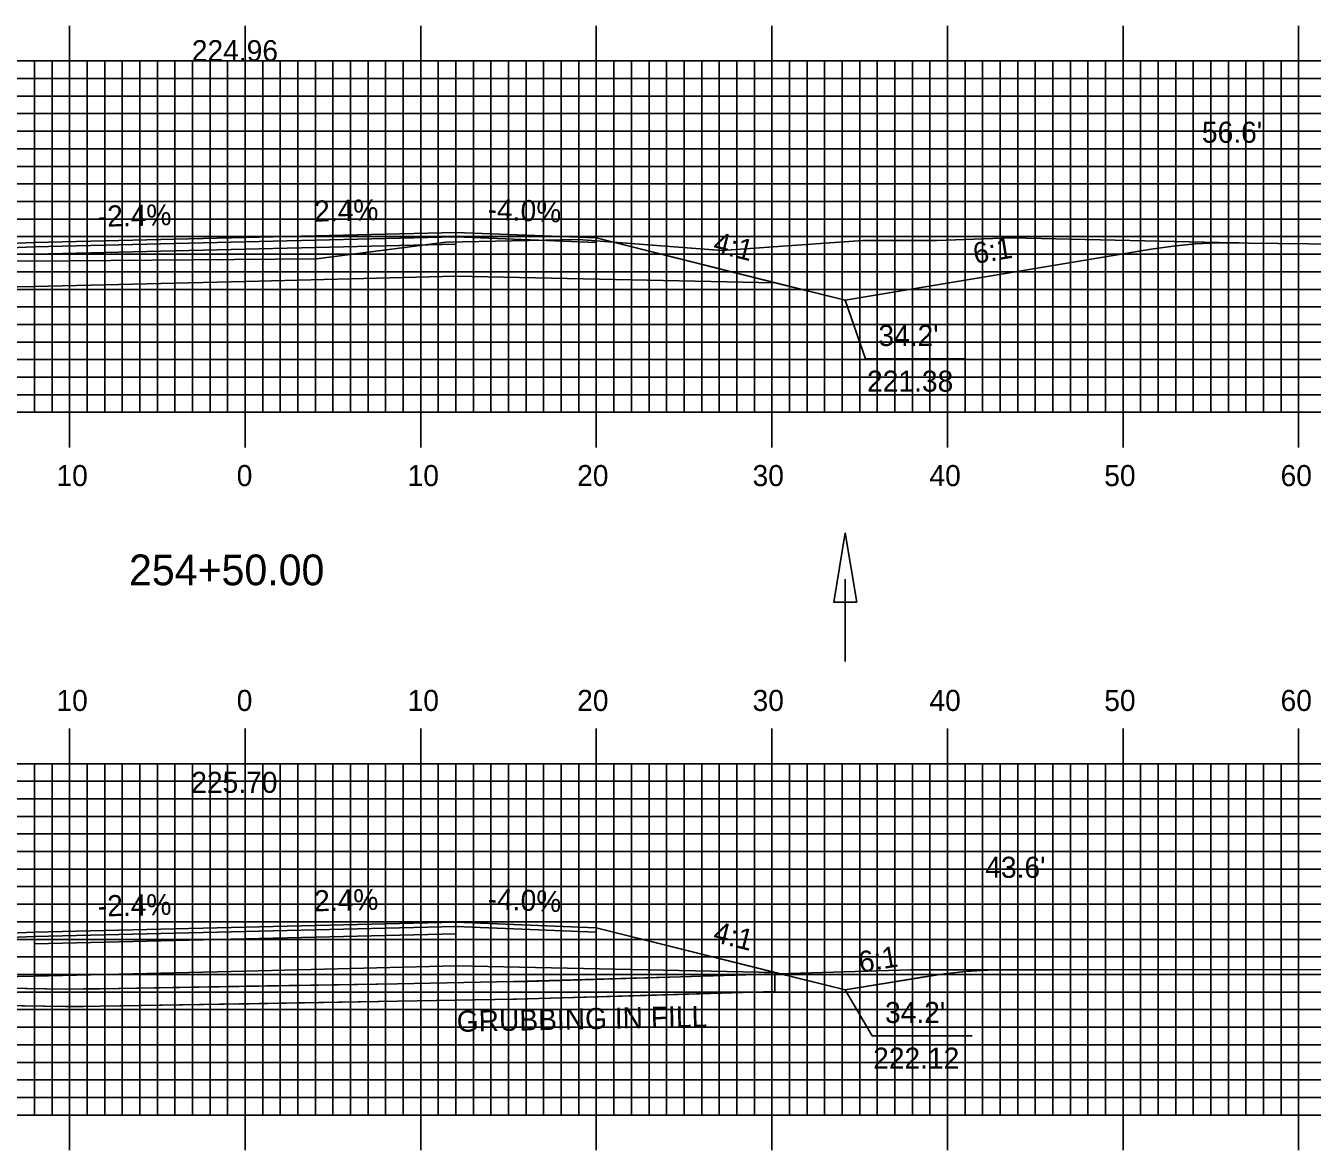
# Model space of a CAD drawing. Extents: x 1804684 to 1805027, y 442591 to 442811.
# Drawn here: x 1804837.2 to 1804910.5, y 442646.7 to 442710.7 of the extents above; entities that cross this region are included whole.
import ezdxf

# ---------------------------------------------------------------- set-up
doc = ezdxf.new("R2010")
doc.units = 0
for name, color, linetype in [('ANNOTATION', 7, 'Continuous'), ('D_Drainage_Ditch_Line', 7, 'Continuous'), ('D_Roadway_Centerline', 7, 'Continuous'), ('D_Roadway_Centerline_Text', 7, 'Continuous'), ('D_Roadway_Edge_Shoulder', 7, 'Continuous'), ('D_Roadway_Edge_TW', 7, 'Continuous'), ('D_Roadway_Pavement', 7, 'Continuous'), ('D_Roadway_SlopeLines', 7, 'Continuous'), ('D_Roadway_SubGrade', 7, 'Continuous'), ('D_Text_Standard', 7, 'Continuous'), ('GRUBBING IN FILL', 7, 'Continuous'), ('H_V ANNOTATION', 7, 'Continuous'), ('MAJOR', 7, 'Continuous'), ('MINOR', 7, 'Continuous'), ('S_Roadway_Centerline', 7, 'Continuous')]:
    doc.layers.add(name, color=color, linetype=linetype)

msp = doc.modelspace()

# ---------------------------------------------------------------- linework, layer by layer
at = {"layer": 'ANNOTATION'}
for points in [[(1804890.701, 442691.713), (1804885.009, 442691.713), (1804883.854, 442695.045)], [(1804891.08, 442653.178), (1804885.388, 442653.178), (1804883.854, 442655.787)]]:
    msp.add_lwpolyline(points, dxfattribs=at)
at = {"layer": 'D_Drainage_Ditch_Line'}
msp.add_line((1804883.855, 442679.177), (1804883.854, 442674.478), dxfattribs=at)
msp.add_lwpolyline([(1804884.511, 442677.865), (1804883.198, 442677.865), (1804883.855, 442681.802)], close=True, dxfattribs=at)
at = {"layer": 'D_Roadway_Centerline'}
for points in [[(1804797.853, 442696.978), (1804799.103, 442696.959), (1804800.353, 442696.886), (1804801.603, 442696.759), (1804802.853, 442696.578), (1804815.506, 442694.469), (1804819.506, 442695.469), (1804829.68, 442698.012), (1804837.68, 442698.332), (1804849.68, 442698.62), (1804861.68, 442698.908), (1804869.68, 442698.588), (1804879.854, 442696.045), (1804883.854, 442695.045), (1804901.287, 442697.95), (1804902.537, 442698.129), (1804903.787, 442698.249), (1804905.037, 442698.31), (1804906.287, 442698.313)], [(1804808.372, 442655.902), (1804809.622, 442655.911), (1804810.872, 442655.859), (1804812.122, 442655.744), (1804813.372, 442655.567), (1804815.506, 442655.211), (1804819.506, 442656.211), (1804829.68, 442658.755), (1804837.68, 442659.075), (1804849.68, 442659.363), (1804861.68, 442659.651), (1804869.68, 442659.331), (1804879.854, 442656.787), (1804883.854, 442655.787), (1804888.235, 442656.517), (1804889.485, 442656.7), (1804890.735, 442656.83), (1804891.985, 442656.909), (1804893.235, 442656.936)]]:
    msp.add_lwpolyline(points, dxfattribs=at)
at = {"layer": 'D_Roadway_Edge_Shoulder'}
for points in [[(1804861.68, 442698.908), (1804869.68, 442698.588), (1804869.68, 442698.338), (1804861.68, 442698.658)], [(1804837.68, 442698.332), (1804829.68, 442698.012), (1804829.68, 442697.762), (1804837.68, 442698.082)], [(1804837.68, 442659.075), (1804829.68, 442658.755), (1804829.68, 442658.505), (1804837.68, 442658.825)], [(1804861.68, 442659.651), (1804869.68, 442659.331), (1804869.68, 442659.081), (1804861.68, 442659.401)]]:
    msp.add_lwpolyline(points, close=True, dxfattribs=at)
at = {"layer": 'D_Roadway_Edge_TW'}
for points in [[(1804837.68, 442698.082), (1804837.68, 442698.332), (1804849.68, 442698.62), (1804861.68, 442698.908), (1804861.68, 442698.658), (1804849.68, 442698.37)], [(1804837.68, 442658.825), (1804837.68, 442659.075), (1804849.68, 442659.363), (1804861.68, 442659.651), (1804861.68, 442659.401), (1804849.68, 442659.113)]]:
    msp.add_lwpolyline(points, close=True, dxfattribs=at)
at = {"layer": 'D_Roadway_Pavement'}
for points in [[(1804837.68, 442697.666), (1804837.68, 442698.082), (1804849.68, 442698.37), (1804861.68, 442698.658), (1804861.68, 442698.242), (1804849.68, 442697.954)], [(1804837.68, 442658.408), (1804837.68, 442658.825), (1804849.68, 442659.113), (1804861.68, 442659.401), (1804861.68, 442658.984), (1804849.68, 442658.696)]]:
    msp.add_lwpolyline(points, close=True, dxfattribs=at)
at = {"layer": 'D_Roadway_SlopeLines'}
for points in [[(1804869.68, 442698.588), (1804883.854, 442695.045)], [(1804883.854, 442695.045), (1804901.287, 442697.95), (1804902.537, 442698.129), (1804903.787, 442698.249), (1804905.037, 442698.31), (1804906.287, 442698.313)], [(1804869.68, 442659.331), (1804883.854, 442655.787)], [(1804883.854, 442655.787), (1804888.235, 442656.517), (1804889.485, 442656.7), (1804890.735, 442656.83), (1804891.985, 442656.909), (1804893.235, 442656.936)], [(1804883.854, 442655.787), (1804889.485, 442656.7), (1804890.735, 442656.83), (1804891.985, 442656.909), (1804893.235, 442656.936)]]:
    msp.add_lwpolyline(points, dxfattribs=at)
at = {"layer": 'D_Roadway_SubGrade'}
for points in [[(1804837.68, 442695.832), (1804819.506, 442695.469), (1804829.68, 442698.012), (1804829.68, 442697.762), (1804837.68, 442698.082), (1804849.68, 442698.37), (1804861.68, 442698.658), (1804869.68, 442698.338), (1804869.68, 442698.588), (1804879.854, 442696.045), (1804861.68, 442696.408), (1804849.68, 442696.12)], [(1804837.68, 442656.574), (1804819.506, 442656.211), (1804829.68, 442658.755), (1804829.68, 442658.505), (1804837.68, 442658.825), (1804849.68, 442659.113), (1804861.68, 442659.401), (1804869.68, 442659.081), (1804869.68, 442659.331), (1804879.854, 442656.787), (1804861.68, 442657.15), (1804849.68, 442656.862)]]:
    msp.add_lwpolyline(points, close=True, dxfattribs=at)
at = {"layer": 'GRUBBING IN FILL'}
msp.add_line((1804879.854, 442656.699), (1804879.854, 442655.698), dxfattribs=at)
msp.add_line((1804879.854, 442656.699), (1804879.854, 442655.698), dxfattribs=at)
for points in [[(1804819.506, 442656.161), (1804828.421, 442656.017), (1804839.457, 442655.839), (1804841.418, 442655.854), (1804849.68, 442655.995), (1804849.68, 442654.995), (1804841.429, 442654.854), (1804839.454, 442654.839), (1804829.48, 442655), (1804819.506, 442655.161)], [(1804819.506, 442656.161), (1804828.421, 442656.017), (1804839.457, 442655.839), (1804841.418, 442655.854), (1804849.68, 442655.995), (1804849.68, 442654.995), (1804841.429, 442654.854), (1804839.454, 442654.839), (1804829.48, 442655), (1804819.506, 442655.161)], [(1804849.68, 442655.995), (1804858.363, 442656.143), (1804864.965, 442656.263), (1804874.47, 442656.536), (1804879.854, 442656.699), (1804879.854, 442655.698), (1804872.498, 442655.476), (1804865.047, 442655.258), (1804861.666, 442655.203), (1804858.38, 442655.143), (1804849.905, 442654.999), (1804849.68, 442654.995)], [(1804849.68, 442655.995), (1804858.363, 442656.143), (1804864.965, 442656.263), (1804874.47, 442656.536), (1804879.854, 442656.699), (1804879.854, 442655.698), (1804872.498, 442655.476), (1804865.047, 442655.258), (1804861.666, 442655.203), (1804858.38, 442655.143), (1804849.905, 442654.999), (1804849.68, 442654.995)]]:
    msp.add_lwpolyline(points, close=True, dxfattribs=at)
msp.add_lwpolyline([(1804819.506, 442655.161), (1804839.454, 442654.839), (1804840.476, 442654.849), (1804841.429, 442654.854), (1804858.38, 442655.143), (1804864.952, 442655.262), (1804865.142, 442655.254), (1804879.854, 442655.698)], dxfattribs=at)
msp.add_lwpolyline([(1804819.506, 442655.161), (1804839.454, 442654.839), (1804840.476, 442654.849), (1804841.429, 442654.854), (1804858.38, 442655.143), (1804864.952, 442655.262), (1804865.142, 442655.254), (1804879.854, 442655.698)], dxfattribs=at)
at = {"layer": 'MAJOR'}
for p, q in [((1804839.68, 442710.669), (1804839.68, 442708.665)), ((1804849.68, 442710.669), (1804849.68, 442708.665)), ((1804859.68, 442710.669), (1804859.68, 442708.665)), ((1804869.68, 442710.669), (1804869.68, 442708.665)), ((1804879.68, 442710.669), (1804879.68, 442708.665)), ((1804889.68, 442710.669), (1804889.68, 442708.665)), ((1804899.68, 442710.669), (1804899.68, 442708.665)), ((1804909.68, 442710.669), (1804909.68, 442708.665)), ((1804709.68, 442708.665), (1804989.68, 442708.665)), ((1804709.68, 442708.665), (1804989.68, 442708.665)), ((1804839.68, 442688.665), (1804839.68, 442708.665)), ((1804849.68, 442688.665), (1804849.68, 442708.665)), ((1804859.68, 442688.665), (1804859.68, 442708.665)), ((1804869.68, 442688.665), (1804869.68, 442708.665)), ((1804879.68, 442688.665), (1804879.68, 442708.665)), ((1804889.68, 442688.665), (1804889.68, 442708.665)), ((1804899.68, 442688.665), (1804899.68, 442708.665)), ((1804909.68, 442688.665), (1804909.68, 442708.665)), ((1804709.68, 442703.665), (1804989.68, 442703.665)), ((1804709.68, 442698.665), (1804989.68, 442698.665)), ((1804709.68, 442693.665), (1804989.68, 442693.665)), ((1804709.68, 442688.665), (1804989.68, 442688.665)), ((1804709.68, 442688.665), (1804989.68, 442688.665)), ((1804839.68, 442686.661), (1804839.68, 442688.665)), ((1804849.68, 442686.661), (1804849.68, 442688.665)), ((1804859.68, 442686.661), (1804859.68, 442688.665)), ((1804869.68, 442686.661), (1804869.68, 442688.665)), ((1804879.68, 442686.661), (1804879.68, 442688.665)), ((1804889.68, 442686.661), (1804889.68, 442688.665)), ((1804899.68, 442686.661), (1804899.68, 442688.665)), ((1804909.68, 442686.661), (1804909.68, 442688.665)), ((1804839.68, 442670.669), (1804839.68, 442668.665)), ((1804849.68, 442670.669), (1804849.68, 442668.665)), ((1804859.68, 442670.669), (1804859.68, 442668.665)), ((1804869.68, 442670.669), (1804869.68, 442668.665)), ((1804879.68, 442670.669), (1804879.68, 442668.665)), ((1804889.68, 442670.669), (1804889.68, 442668.665)), ((1804899.68, 442670.669), (1804899.68, 442668.665)), ((1804909.68, 442670.669), (1804909.68, 442668.665)), ((1804709.68, 442668.665), (1804989.68, 442668.665)), ((1804709.68, 442668.665), (1804989.68, 442668.665)), ((1804839.68, 442648.665), (1804839.68, 442668.665)), ((1804849.68, 442648.665), (1804849.68, 442668.665)), ((1804859.68, 442648.665), (1804859.68, 442668.665)), ((1804869.68, 442648.665), (1804869.68, 442668.665)), ((1804879.68, 442648.665), (1804879.68, 442668.665)), ((1804889.68, 442648.665), (1804889.68, 442668.665)), ((1804899.68, 442648.665), (1804899.68, 442668.665)), ((1804909.68, 442648.665), (1804909.68, 442668.665)), ((1804709.68, 442663.665), (1804989.68, 442663.665)), ((1804709.68, 442658.665), (1804989.68, 442658.665)), ((1804709.68, 442653.665), (1804989.68, 442653.665)), ((1804709.68, 442648.665), (1804989.68, 442648.665)), ((1804709.68, 442648.665), (1804989.68, 442648.665)), ((1804839.68, 442646.661), (1804839.68, 442648.665)), ((1804849.68, 442646.661), (1804849.68, 442648.665)), ((1804859.68, 442646.661), (1804859.68, 442648.665)), ((1804869.68, 442646.661), (1804869.68, 442648.665)), ((1804879.68, 442646.661), (1804879.68, 442648.665)), ((1804889.68, 442646.661), (1804889.68, 442648.665)), ((1804899.68, 442646.661), (1804899.68, 442648.665)), ((1804909.68, 442646.661), (1804909.68, 442648.665))]:
    msp.add_line(p, q, dxfattribs=at)
at = {"layer": 'MINOR'}
for p, q in [((1804837.68, 442688.665), (1804837.68, 442708.665)), ((1804838.68, 442688.665), (1804838.68, 442708.665)), ((1804840.68, 442688.665), (1804840.68, 442708.665)), ((1804841.68, 442688.665), (1804841.68, 442708.665)), ((1804842.68, 442688.665), (1804842.68, 442708.665)), ((1804843.68, 442688.665), (1804843.68, 442708.665)), ((1804844.68, 442688.665), (1804844.68, 442708.665)), ((1804845.68, 442688.665), (1804845.68, 442708.665)), ((1804846.68, 442688.665), (1804846.68, 442708.665)), ((1804847.68, 442688.665), (1804847.68, 442708.665)), ((1804848.68, 442688.665), (1804848.68, 442708.665)), ((1804850.68, 442688.665), (1804850.68, 442708.665)), ((1804851.68, 442688.665), (1804851.68, 442708.665)), ((1804852.68, 442688.665), (1804852.68, 442708.665)), ((1804853.68, 442688.665), (1804853.68, 442708.665)), ((1804854.68, 442688.665), (1804854.68, 442708.665)), ((1804855.68, 442688.665), (1804855.68, 442708.665)), ((1804856.68, 442688.665), (1804856.68, 442708.665)), ((1804857.68, 442688.665), (1804857.68, 442708.665)), ((1804858.68, 442688.665), (1804858.68, 442708.665)), ((1804860.68, 442688.665), (1804860.68, 442708.665)), ((1804861.68, 442688.665), (1804861.68, 442708.665)), ((1804862.68, 442688.665), (1804862.68, 442708.665)), ((1804863.68, 442688.665), (1804863.68, 442708.665)), ((1804864.68, 442688.665), (1804864.68, 442708.665)), ((1804865.68, 442688.665), (1804865.68, 442708.665)), ((1804866.68, 442688.665), (1804866.68, 442708.665)), ((1804867.68, 442688.665), (1804867.68, 442708.665)), ((1804868.68, 442688.665), (1804868.68, 442708.665)), ((1804870.68, 442688.665), (1804870.68, 442708.665)), ((1804871.68, 442688.665), (1804871.68, 442708.665)), ((1804872.68, 442688.665), (1804872.68, 442708.665)), ((1804873.68, 442688.665), (1804873.68, 442708.665)), ((1804874.68, 442688.665), (1804874.68, 442708.665)), ((1804875.68, 442688.665), (1804875.68, 442708.665)), ((1804876.68, 442688.665), (1804876.68, 442708.665)), ((1804877.68, 442688.665), (1804877.68, 442708.665)), ((1804878.68, 442688.665), (1804878.68, 442708.665)), ((1804880.68, 442688.665), (1804880.68, 442708.665)), ((1804881.68, 442688.665), (1804881.68, 442708.665)), ((1804882.68, 442688.665), (1804882.68, 442708.665)), ((1804883.68, 442688.665), (1804883.68, 442708.665)), ((1804884.68, 442688.665), (1804884.68, 442708.665)), ((1804885.68, 442688.665), (1804885.68, 442708.665)), ((1804886.68, 442688.665), (1804886.68, 442708.665)), ((1804887.68, 442688.665), (1804887.68, 442708.665)), ((1804888.68, 442688.665), (1804888.68, 442708.665)), ((1804890.68, 442688.665), (1804890.68, 442708.665)), ((1804891.68, 442688.665), (1804891.68, 442708.665)), ((1804892.68, 442688.665), (1804892.68, 442708.665)), ((1804893.68, 442688.665), (1804893.68, 442708.665)), ((1804894.68, 442688.665), (1804894.68, 442708.665)), ((1804895.68, 442688.665), (1804895.68, 442708.665)), ((1804896.68, 442688.665), (1804896.68, 442708.665)), ((1804897.68, 442688.665), (1804897.68, 442708.665)), ((1804898.68, 442688.665), (1804898.68, 442708.665)), ((1804900.68, 442688.665), (1804900.68, 442708.665)), ((1804901.68, 442688.665), (1804901.68, 442708.665)), ((1804902.68, 442688.665), (1804902.68, 442708.665)), ((1804903.68, 442688.665), (1804903.68, 442708.665)), ((1804904.68, 442688.665), (1804904.68, 442708.665)), ((1804905.68, 442688.665), (1804905.68, 442708.665)), ((1804906.68, 442688.665), (1804906.68, 442708.665)), ((1804907.68, 442688.665), (1804907.68, 442708.665)), ((1804908.68, 442688.665), (1804908.68, 442708.665)), ((1804709.68, 442707.665), (1804989.68, 442707.665)), ((1804709.68, 442706.665), (1804989.68, 442706.665)), ((1804709.68, 442705.665), (1804989.68, 442705.665)), ((1804709.68, 442704.665), (1804989.68, 442704.665)), ((1804709.68, 442702.665), (1804989.68, 442702.665)), ((1804709.68, 442701.665), (1804989.68, 442701.665)), ((1804709.68, 442700.665), (1804989.68, 442700.665)), ((1804709.68, 442699.665), (1804989.68, 442699.665)), ((1804709.68, 442697.665), (1804989.68, 442697.665)), ((1804709.68, 442696.665), (1804989.68, 442696.665)), ((1804709.68, 442695.665), (1804989.68, 442695.665)), ((1804709.68, 442694.665), (1804989.68, 442694.665)), ((1804709.68, 442692.665), (1804989.68, 442692.665)), ((1804709.68, 442691.665), (1804989.68, 442691.665)), ((1804709.68, 442690.665), (1804989.68, 442690.665)), ((1804709.68, 442689.665), (1804989.68, 442689.665)), ((1804837.68, 442648.665), (1804837.68, 442668.665)), ((1804838.68, 442648.665), (1804838.68, 442668.665)), ((1804840.68, 442648.665), (1804840.68, 442668.665)), ((1804841.68, 442648.665), (1804841.68, 442668.665)), ((1804842.68, 442648.665), (1804842.68, 442668.665)), ((1804843.68, 442648.665), (1804843.68, 442668.665)), ((1804844.68, 442648.665), (1804844.68, 442668.665)), ((1804845.68, 442648.665), (1804845.68, 442668.665)), ((1804846.68, 442648.665), (1804846.68, 442668.665)), ((1804847.68, 442648.665), (1804847.68, 442668.665)), ((1804848.68, 442648.665), (1804848.68, 442668.665)), ((1804850.68, 442648.665), (1804850.68, 442668.665)), ((1804851.68, 442648.665), (1804851.68, 442668.665)), ((1804852.68, 442648.665), (1804852.68, 442668.665)), ((1804853.68, 442648.665), (1804853.68, 442668.665)), ((1804854.68, 442648.665), (1804854.68, 442668.665)), ((1804855.68, 442648.665), (1804855.68, 442668.665)), ((1804856.68, 442648.665), (1804856.68, 442668.665)), ((1804857.68, 442648.665), (1804857.68, 442668.665)), ((1804858.68, 442648.665), (1804858.68, 442668.665)), ((1804860.68, 442648.665), (1804860.68, 442668.665)), ((1804861.68, 442648.665), (1804861.68, 442668.665)), ((1804862.68, 442648.665), (1804862.68, 442668.665)), ((1804863.68, 442648.665), (1804863.68, 442668.665)), ((1804864.68, 442648.665), (1804864.68, 442668.665)), ((1804865.68, 442648.665), (1804865.68, 442668.665)), ((1804866.68, 442648.665), (1804866.68, 442668.665)), ((1804867.68, 442648.665), (1804867.68, 442668.665)), ((1804868.68, 442648.665), (1804868.68, 442668.665)), ((1804870.68, 442648.665), (1804870.68, 442668.665)), ((1804871.68, 442648.665), (1804871.68, 442668.665)), ((1804872.68, 442648.665), (1804872.68, 442668.665)), ((1804873.68, 442648.665), (1804873.68, 442668.665)), ((1804874.68, 442648.665), (1804874.68, 442668.665)), ((1804875.68, 442648.665), (1804875.68, 442668.665)), ((1804876.68, 442648.665), (1804876.68, 442668.665)), ((1804877.68, 442648.665), (1804877.68, 442668.665)), ((1804878.68, 442648.665), (1804878.68, 442668.665)), ((1804880.68, 442648.665), (1804880.68, 442668.665)), ((1804881.68, 442648.665), (1804881.68, 442668.665)), ((1804882.68, 442648.665), (1804882.68, 442668.665)), ((1804883.68, 442648.665), (1804883.68, 442668.665)), ((1804884.68, 442648.665), (1804884.68, 442668.665)), ((1804885.68, 442648.665), (1804885.68, 442668.665)), ((1804886.68, 442648.665), (1804886.68, 442668.665)), ((1804887.68, 442648.665), (1804887.68, 442668.665)), ((1804888.68, 442648.665), (1804888.68, 442668.665)), ((1804890.68, 442648.665), (1804890.68, 442668.665)), ((1804891.68, 442648.665), (1804891.68, 442668.665)), ((1804892.68, 442648.665), (1804892.68, 442668.665)), ((1804893.68, 442648.665), (1804893.68, 442668.665)), ((1804894.68, 442648.665), (1804894.68, 442668.665)), ((1804895.68, 442648.665), (1804895.68, 442668.665)), ((1804896.68, 442648.665), (1804896.68, 442668.665)), ((1804897.68, 442648.665), (1804897.68, 442668.665)), ((1804898.68, 442648.665), (1804898.68, 442668.665)), ((1804900.68, 442648.665), (1804900.68, 442668.665)), ((1804901.68, 442648.665), (1804901.68, 442668.665)), ((1804902.68, 442648.665), (1804902.68, 442668.665)), ((1804903.68, 442648.665), (1804903.68, 442668.665)), ((1804904.68, 442648.665), (1804904.68, 442668.665)), ((1804905.68, 442648.665), (1804905.68, 442668.665)), ((1804906.68, 442648.665), (1804906.68, 442668.665)), ((1804907.68, 442648.665), (1804907.68, 442668.665)), ((1804908.68, 442648.665), (1804908.68, 442668.665)), ((1804709.68, 442667.665), (1804989.68, 442667.665)), ((1804709.68, 442666.665), (1804989.68, 442666.665)), ((1804709.68, 442665.665), (1804989.68, 442665.665)), ((1804709.68, 442664.665), (1804989.68, 442664.665)), ((1804709.68, 442662.665), (1804989.68, 442662.665)), ((1804709.68, 442661.665), (1804989.68, 442661.665)), ((1804709.68, 442660.665), (1804989.68, 442660.665)), ((1804709.68, 442659.665), (1804989.68, 442659.665)), ((1804709.68, 442657.665), (1804989.68, 442657.665)), ((1804709.68, 442656.665), (1804989.68, 442656.665)), ((1804709.68, 442655.665), (1804989.68, 442655.665)), ((1804709.68, 442654.665), (1804989.68, 442654.665)), ((1804709.68, 442652.665), (1804989.68, 442652.665)), ((1804709.68, 442651.665), (1804989.68, 442651.665)), ((1804709.68, 442650.665), (1804989.68, 442650.665)), ((1804709.68, 442649.665), (1804989.68, 442649.665))]:
    msp.add_line(p, q, dxfattribs=at)
at = {"layer": 'S_Roadway_Centerline'}
for points in [[(1804774.867, 442696.859), (1804784.246, 442696.939), (1804798.892, 442696.981), (1804806.635, 442697.05), (1804815.328, 442697.213), (1804821.412, 442697.283), (1804829.591, 442697.328), (1804837.339, 442697.271), (1804853.743, 442697.409), (1804861.115, 442698.351), (1804868.67, 442698.496), (1804876.823, 442697.877), (1804884.86, 442698.445), (1804889.076, 442698.448), (1804893.324, 442698.594), (1804906.832, 442698.301), (1804911.958, 442698.237)], [(1804772.616, 442656.11), (1804784.021, 442655.571), (1804795.945, 442655.762), (1804806.455, 442655.84), (1804817.384, 442656.195), (1804839.457, 442655.839), (1804840.468, 442655.849), (1804841.418, 442655.854), (1804858.363, 442656.143), (1804864.965, 442656.263), (1804865.149, 442656.255), (1804883.79, 442656.818), (1804887.568, 442656.929), (1804887.617, 442656.931), (1804887.639, 442656.931), (1804895.71, 442656.938), (1804911.532, 442656.95)]]:
    msp.add_lwpolyline(points, dxfattribs=at)

# ---------------------------------------------------------------- texts
at = {"layer": 'ANNOTATION'}
for s, rotation, p in [('-2.4%', 1.37483, (1804841.3, 442699.22)), ('2.4%', 1.37483, (1804853.621, 442699.516)), ('-4.0%', 357.70939, (1804863.472, 442699.638)), ('4:1', 345.96376, (1804876.273, 442697.802)), ('6:1', 9.46235, (1804891.246, 442697.104)), ('2.4%', 1.37483, (1804853.621, 442660.258)), ('-4.0%', 357.70939, (1804863.472, 442660.38)), ('-2.4%', 1.37483, (1804841.3, 442659.962)), ('4:1', 345.96376, (1804876.273, 442658.544)), ('6:1', 9.46232, (1804884.72, 442656.759))]:
    msp.add_text(s, height=1.2, rotation=rotation, dxfattribs=at).set_placement(p)
for s, p in [("34.2'", (1804885.744, 442692.439)), ('221.38', (1804885.102, 442689.839)), ("34.2'", (1804886.123, 442653.904)), ('222.12', (1804885.448, 442651.304))]:
    msp.add_text(s, height=1.2, dxfattribs=at).set_placement(p)
at = {"layer": 'D_Roadway_Centerline'}
for s, p in [('C', (1804849.675, 442698.62)), ('L', (1804849.68, 442698.613)), ('C', (1804849.675, 442659.363)), ('L', (1804849.68, 442659.355))]:
    msp.add_text(s, height=0.0146, dxfattribs=at).set_placement(p)
at = {"layer": 'D_Roadway_Centerline_Text'}
for s, p in [('224.96', (1804846.641, 442708.65)), ('225.70', (1804846.608, 442667.004))]:
    msp.add_text(s, height=1.2, dxfattribs=at).set_placement(p)
at = {"layer": 'D_Text_Standard'}
for s, p in [("56.6'", (1804904.173, 442704.007)), ("43.6'", (1804891.832, 442662.168))]:
    msp.add_text(s, height=1.2, dxfattribs=at).set_placement(p)
at = {"layer": 'GRUBBING IN FILL'}
msp.add_text('GRUBBING IN FILL', height=1.2, rotation=1.16831, dxfattribs=at).set_placement((1804861.74, 442653.398))
at = {"layer": 'H_V ANNOTATION'}
for s, height, p in [('10', 1.2, (1804838.931, 442684.465)), ('0', 1.2, (1804849.198, 442684.465)), ('10', 1.2, (1804858.931, 442684.465)), ('20', 1.2, (1804868.588, 442684.465)), ('30', 1.2, (1804878.578, 442684.465)), ('40', 1.2, (1804888.653, 442684.465)), ('50', 1.2, (1804898.61, 442684.465)), ('60', 1.2, (1804908.653, 442684.465)), ('254+50.00', 1.75, (1804843.063, 442678.821)), ('10', 1.2, (1804838.931, 442671.665)), ('0', 1.2, (1804849.198, 442671.665)), ('10', 1.2, (1804858.931, 442671.665)), ('20', 1.2, (1804868.588, 442671.665)), ('30', 1.2, (1804878.578, 442671.665)), ('40', 1.2, (1804888.653, 442671.665)), ('50', 1.2, (1804898.61, 442671.665)), ('60', 1.2, (1804908.653, 442671.665))]:
    msp.add_text(s, height=height, dxfattribs=at).set_placement(p)

doc.saveas('drawing.dxf')
